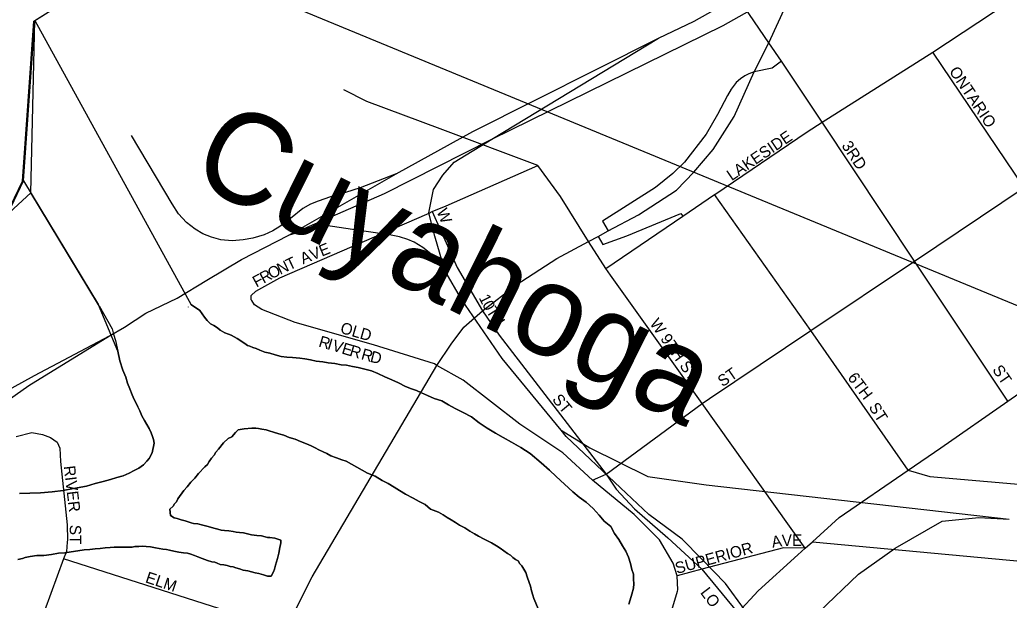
# Model space of a CAD drawing. Extents: x -561 to 1170, y 0 to 846.
# Drawn here: x 229.07 to 240.77, y 285.96 to 292.82 of the extents above; entities that cross this region are included whole.
import ezdxf

# ---------------------------------------------------------------- set-up
doc = ezdxf.new("R2010")
doc.units = 0
for name, color, linetype in [('GM_X_City_Street', 7, 'Continuous'), ('GM_X_City_Street_Text', 7, 'Continuous'), ('GM_X_County', 7, 'Continuous'), ('GM_X_Interchange_Ramps', 7, 'Continuous'), ('GM_X_Major_Lake', 7, 'Continuous'), ('GM_X_Major_River', 7, 'Continuous'), ('GM_X_Major_River_Text', 7, 'Continuous'), ('GM_X_Rail_Line', 7, 'Continuous'), ('GM_X_State_Route', 7, 'Continuous'), ('GM_X_US_Route', 7, 'Continuous'), ('SH_Text', 7, 'Continuous')]:
    doc.layers.add(name, color=color, linetype=linetype)

msp = doc.modelspace()

# ---------------------------------------------------------------- linework, layer by layer
at = {"layer": 'GM_X_City_Street'}
for points in [[(238.558, 291.607), (239.868, 292.434), (242.363, 294.084), (243.61, 294.998), (245.404, 296.163), (246.416, 296.86), (246.465, 296.891)], [(238.076, 292.33), (237.929, 292.546), (237.294, 293.481), (237.222, 293.588), (237.213, 293.601)], [(237.226, 288.342), (238.426, 289.146), (239.65, 289.967), (240.947, 290.836), (243.453, 292.515), (244.706, 293.355)], [(240.969, 290.804), (240.947, 290.836), (239.868, 292.434)], [(238.558, 291.607), (238.076, 292.33)], [(234.043, 291.529), (233.176, 291.853), (232.904, 291.99)], [(235.196, 291.097), (234.043, 291.529)], [(237.289, 290.754), (238.379, 291.494), (238.558, 291.607)], [(240.754, 288.31), (239.65, 289.967), (238.558, 291.607)], [(233.911, 290.535), (233.949, 290.551), (234.111, 290.621), (235.196, 291.097)], [(236.056, 289.8), (235.999, 289.879), (235.797, 290.199), (235.463, 290.729), (235.196, 291.097)], [(236.909, 290.496), (237.286, 290.752), (237.289, 290.754)], [(239.574, 287.497), (238.426, 289.146), (237.286, 290.752)], [(231.815, 289.501), (231.809, 289.51), (231.809, 289.536), (231.809, 289.562), (231.861, 289.613), (232.145, 289.768), (233.886, 290.523), (233.911, 290.535)], [(233.949, 290.551), (234.242, 289.89), (234.542, 289.378), (234.738, 289.09), (236.005, 287.447)], [(235.999, 289.879), (236.909, 290.496)], [(238.358, 286.573), (237.138, 288.283), (236.056, 289.8)], [(235.844, 287.379), (235.491, 287.701), (234.983, 288.04), (234.313, 288.558), (234.004, 288.734), (233.975, 288.751), (233.253, 288.978), (232.327, 289.24), (231.935, 289.394), (231.847, 289.45), (231.815, 289.501)], [(235.844, 287.379), (236.005, 287.447), (237.138, 288.283), (237.226, 288.342)], [(229.029, 287.896), (229.214, 287.941), (229.341, 287.919), (229.434, 287.884), (229.513, 287.827), (229.544, 287.756), (229.553, 287.6), (229.632, 286.849), (229.636, 286.673), (229.634, 286.644)], [(236.005, 287.447), (236.122, 287.273), (236.34, 287.041), (236.733, 286.696), (237.137, 286.325), (237.56, 285.809), (237.794, 285.486), (238.12, 284.963)], [(239.574, 287.497), (239.829, 287.421), (241.875, 287.246)], [(236.847, 286.065), (236.852, 286.081), (236.844, 286.246), (236.796, 286.398), (236.635, 286.673), (236.334, 286.974), (235.844, 287.379)], [(229.634, 286.644), (229.623, 286.536), (229.588, 286.448), (229.364, 285.836)], [(238.444, 286.651), (244.34, 286.102), (244.643, 286.223)], [(238.358, 286.573), (238.1, 286.579), (237.137, 286.325), (236.844, 286.246)], [(232.413, 285.545), (232.215, 285.608), (229.588, 286.448)], [(236.424, 284.721), (236.471, 284.895), (236.475, 284.911), (236.703, 285.579), (236.847, 286.065)]]:
    msp.add_lwpolyline(points, dxfattribs=at)
at = {"layer": 'GM_X_County'}
msp.add_lwpolyline([(228.917, 290.518), (229.103, 290.91), (229.239, 292.802), (229.767, 293.137), (230.178, 293.098), (230.519, 293.193), (230.927, 293.516), (231.298, 293.866), (231.437, 294.095), (231.451, 294.274), (239.814, 300.702), (242.553, 303.852)], dxfattribs=at)
at = {"layer": 'GM_X_Interchange_Ramps'}
for points in [[(238.076, 292.33), (237.966, 292.245), (237.756, 292.202), (237.692, 292.18), (237.642, 292.155), (237.591, 292.12), (237.543, 292.076), (237.481, 291.997), (237.437, 291.924), (237.321, 291.698), (237.188, 291.466), (236.932, 291.137), (236.793, 291.002), (236.589, 290.838), (235.96, 290.437), (236.029, 290.326)], [(235.909, 290.259), (235.967, 290.162), (236.25, 290.266), (236.887, 290.531), (236.909, 290.496)]]:
    msp.add_lwpolyline(points, dxfattribs=at)
at = {"layer": 'GM_X_Major_Lake'}
msp.add_line((229.201, 290.775), (229.251, 292.809), dxfattribs=at)
for points in [[(226.905, 289.371), (227.507, 289.716), (228.09, 289.927), (228.537, 290.164), (228.929, 290.525), (229.115, 290.917), (229.251, 292.809), (229.779, 293.144), (230.19, 293.104), (230.53, 293.2), (230.939, 293.523), (231.31, 293.873), (231.425, 294.063)], [(229.251, 292.809), (229.779, 293.144), (230.19, 293.104), (230.53, 293.2), (230.939, 293.523), (231.31, 293.873), (231.425, 294.063)], [(226.905, 289.371), (227.507, 289.716), (228.09, 289.927), (228.537, 290.164), (229.201, 290.775)]]:
    msp.add_lwpolyline(points, dxfattribs=at)
at = {"layer": 'GM_X_Major_River'}
for points in [[(229.201, 290.775), (229.251, 292.809)], [(229.251, 292.809), (231.099, 289.45)], [(229.251, 292.809), (231.099, 289.45)], [(229.115, 290.917), (230.001, 289.451)], [(230.001, 289.451), (229.201, 290.775)], [(229.07, 287.221), (229.19, 287.223), (229.319, 287.23), (229.455, 287.242), (229.584, 287.254), (229.708, 287.278), (229.86, 287.307), (229.962, 287.34), (230.059, 287.363), (230.145, 287.386), (230.221, 287.408), (230.296, 287.431), (230.366, 287.459), (230.425, 287.492), (230.479, 287.52), (230.533, 287.558), (230.575, 287.602), (230.602, 287.635), (230.639, 287.701), (230.659, 287.815), (230.653, 287.858), (230.642, 287.896), (230.625, 287.939), (230.603, 287.987), (230.575, 288.036), (230.547, 288.084), (230.514, 288.138), (230.492, 288.197), (230.469, 288.246), (230.447, 288.289), (230.425, 288.332), (230.402, 288.386), (230.374, 288.456), (230.346, 288.526), (230.324, 288.596), (230.29, 288.677), (230.256, 288.79), (230.233, 288.904), (230.001, 289.451)], [(230.01, 289.44), (230.164, 289.168), (230.181, 289.104), (230.204, 289.028), (230.233, 288.904), (230.256, 288.79), (230.29, 288.677), (230.324, 288.596), (230.346, 288.526), (230.374, 288.456), (230.402, 288.386), (230.425, 288.332), (230.447, 288.289), (230.469, 288.246), (230.492, 288.197), (230.514, 288.138), (230.547, 288.084), (230.575, 288.036), (230.603, 287.987), (230.625, 287.939), (230.642, 287.896), (230.653, 287.858), (230.659, 287.815), (230.639, 287.701), (230.602, 287.635), (230.575, 287.602), (230.533, 287.558), (230.479, 287.52), (230.425, 287.492), (230.366, 287.459), (230.296, 287.431), (230.221, 287.408), (230.145, 287.386), (230.059, 287.363), (229.962, 287.34), (229.86, 287.307), (229.708, 287.278), (229.584, 287.254), (229.455, 287.242), (229.319, 287.23), (229.19, 287.223), (229.07, 287.221)], [(231.063, 289.427), (231.062, 289.422)], [(236.333, 286.155), (236.327, 286.209), (236.326, 286.269), (236.309, 286.323), (236.292, 286.393), (236.269, 286.469), (236.236, 286.539), (236.197, 286.603), (236.153, 286.678), (236.103, 286.748), (236.059, 286.829), (235.982, 286.893), (235.921, 286.963), (235.85, 287.043), (235.768, 287.118), (235.686, 287.177), (235.609, 287.241), (235.412, 287.423), (235.335, 287.497), (235.236, 287.583), (235.105, 287.695), (234.996, 287.764), (234.887, 287.828), (234.788, 287.881), (234.696, 287.934), (234.597, 287.992), (234.505, 288.056), (234.412, 288.125), (234.313, 288.178), (234.221, 288.226), (234.139, 288.268), (234.063, 288.316), (233.97, 288.342), (233.894, 288.379), (233.823, 288.411), (233.763, 288.437), (233.703, 288.458), (233.633, 288.484), (233.551, 288.527), (233.469, 288.564), (233.387, 288.601), (233.306, 288.638), (233.229, 288.669), (233.137, 288.695), (233.072, 288.711), (233.007, 288.721), (232.936, 288.736), (232.871, 288.741), (232.795, 288.756), (232.719, 288.766), (232.654, 288.776), (232.578, 288.786), (232.508, 288.801), (232.443, 288.811), (232.383, 288.821), (232.296, 288.826), (232.231, 288.83), (232.161, 288.84), (232.09, 288.861), (232.03, 288.877), (231.971, 288.892), (231.911, 288.913), (231.867, 288.934), (231.829, 288.945), (231.791, 288.961), (231.764, 288.971), (231.731, 288.992), (231.644, 289.051), (231.605, 289.072), (231.573, 289.093), (231.54, 289.104), (231.497, 289.12), (231.442, 289.151), (231.409, 289.178), (231.365, 289.205), (231.327, 289.226), (231.289, 289.263), (231.256, 289.306), (231.228, 289.344), (231.201, 289.381), (231.103, 289.45)], [(231.103, 289.45), (231.201, 289.381), (231.228, 289.344), (231.256, 289.306), (231.289, 289.263), (231.327, 289.226), (231.365, 289.205), (231.409, 289.178), (231.442, 289.151), (231.497, 289.12), (231.54, 289.104), (231.573, 289.093), (231.605, 289.072), (231.644, 289.051), (231.731, 288.992), (231.764, 288.971), (231.791, 288.961), (231.829, 288.945), (231.867, 288.934), (231.911, 288.913), (231.971, 288.892), (232.03, 288.877), (232.09, 288.861), (232.161, 288.84), (232.231, 288.83), (232.296, 288.826), (232.383, 288.821), (232.443, 288.811), (232.508, 288.801), (232.578, 288.786), (232.654, 288.776), (232.719, 288.766), (232.795, 288.756), (232.871, 288.741), (232.936, 288.736), (233.007, 288.721), (233.072, 288.711), (233.137, 288.695), (233.229, 288.669), (233.306, 288.638), (233.387, 288.601), (233.469, 288.564), (233.551, 288.527), (233.633, 288.484), (233.703, 288.458), (233.763, 288.437), (233.823, 288.411), (233.894, 288.379), (233.97, 288.342), (234.063, 288.316), (234.139, 288.268), (234.221, 288.226), (234.313, 288.178), (234.412, 288.125), (234.505, 288.056), (234.597, 287.992), (234.696, 287.934), (234.788, 287.881), (234.887, 287.828), (234.996, 287.764), (235.105, 287.695), (235.236, 287.583), (235.335, 287.497), (235.412, 287.423), (235.609, 287.241), (235.686, 287.177), (235.768, 287.118), (235.85, 287.043), (235.921, 286.963), (235.982, 286.893), (236.059, 286.829), (236.103, 286.748), (236.153, 286.678), (236.197, 286.603), (236.236, 286.539), (236.269, 286.469), (236.292, 286.393), (236.309, 286.323), (236.326, 286.269), (236.327, 286.209), (236.333, 286.155)], [(231.627, 286.342), (231.67, 286.332), (231.714, 286.316), (231.768, 286.306), (231.855, 286.285), (231.898, 286.275), (231.953, 286.259), (232.001, 286.244), (232.045, 286.244), (232.071, 286.293), (232.082, 286.326), (232.097, 286.375), (232.107, 286.413), (232.118, 286.451), (232.128, 286.483), (232.133, 286.516), (232.143, 286.559), (232.148, 286.587), (232.153, 286.614), (232.158, 286.641), (232.158, 286.668), (232.087, 286.694), (232.028, 286.699), (232.001, 286.699), (231.973, 286.709), (231.93, 286.719), (231.876, 286.724), (231.811, 286.734), (231.718, 286.755), (231.67, 286.76), (231.632, 286.765), (231.594, 286.77), (231.545, 286.78), (231.491, 286.785), (231.453, 286.789), (231.415, 286.8), (231.366, 286.81), (231.301, 286.831), (231.235, 286.846), (231.176, 286.862), (231.127, 286.867), (231.1, 286.872), (231.073, 286.882), (231.029, 286.898), (230.98, 286.908), (230.931, 286.924), (230.899, 286.934), (230.855, 286.961), (230.848, 287.037), (230.886, 287.07), (230.902, 287.097), (230.923, 287.124), (230.939, 287.157), (231.013, 287.255), (231.051, 287.299), (231.093, 287.354), (231.141, 287.403), (231.184, 287.458), (231.258, 287.535), (231.291, 287.562), (231.312, 287.6), (231.338, 287.639), (231.37, 287.672), (231.391, 287.71), (231.423, 287.743), (231.482, 287.819), (231.535, 287.869), (231.578, 287.891), (231.621, 287.94), (231.653, 287.973), (231.723, 287.985), (231.815, 287.991), (231.864, 287.992), (231.896, 287.987), (231.934, 287.982), (231.983, 287.972), (232.021, 287.961), (232.07, 287.945), (232.135, 287.925), (232.195, 287.909), (232.255, 287.883), (232.326, 287.862), (232.391, 287.836), (232.462, 287.809), (232.516, 287.783), (232.565, 287.762), (232.609, 287.735), (232.658, 287.714), (232.702, 287.693), (232.751, 287.667), (232.816, 287.64), (232.881, 287.619), (232.93, 287.604), (233.181, 287.46), (233.274, 287.424), (233.355, 287.376), (233.426, 287.339), (233.497, 287.296), (233.563, 287.254), (233.634, 287.211), (233.721, 287.164)], [(233.721, 287.164), (233.634, 287.211), (233.563, 287.254), (233.497, 287.296), (233.426, 287.339), (233.355, 287.376), (233.274, 287.424), (233.181, 287.46), (232.93, 287.604), (232.881, 287.619), (232.816, 287.64), (232.751, 287.667), (232.702, 287.693), (232.658, 287.714), (232.609, 287.735), (232.565, 287.762), (232.516, 287.783), (232.462, 287.809), (232.391, 287.836), (232.326, 287.862), (232.255, 287.883), (232.195, 287.909), (232.135, 287.925), (232.07, 287.945), (232.021, 287.961), (231.983, 287.972), (231.934, 287.982), (231.896, 287.987), (231.864, 287.992), (231.815, 287.991), (231.723, 287.985), (231.653, 287.973), (231.621, 287.94), (231.578, 287.891), (231.535, 287.869), (231.482, 287.819), (231.423, 287.743), (231.391, 287.71), (231.37, 287.672), (231.338, 287.639), (231.312, 287.6), (231.291, 287.562), (231.258, 287.535), (231.184, 287.458), (231.141, 287.403), (231.093, 287.354), (231.051, 287.299), (231.013, 287.255), (230.939, 287.157), (230.923, 287.124), (230.902, 287.097), (230.886, 287.07), (230.848, 287.037), (230.855, 286.961), (230.899, 286.934), (230.931, 286.924), (230.98, 286.908), (231.029, 286.898), (231.073, 286.882), (231.1, 286.872), (231.127, 286.867), (231.176, 286.862), (231.235, 286.846), (231.301, 286.831), (231.366, 286.81), (231.415, 286.8), (231.453, 286.789), (231.491, 286.785), (231.545, 286.78), (231.594, 286.77), (231.632, 286.765), (231.67, 286.76), (231.718, 286.755), (231.811, 286.734), (231.876, 286.724), (231.93, 286.719), (231.973, 286.709), (232.001, 286.699), (232.028, 286.699), (232.087, 286.694), (232.158, 286.668), (232.158, 286.641), (232.153, 286.614), (232.148, 286.587), (232.143, 286.559), (232.133, 286.516), (232.128, 286.483), (232.118, 286.451), (232.107, 286.413), (232.097, 286.375), (232.082, 286.326), (232.071, 286.293), (232.045, 286.244), (232.001, 286.244), (231.953, 286.259), (231.898, 286.275), (231.855, 286.285), (231.768, 286.306), (231.714, 286.316), (231.67, 286.332), (231.627, 286.342)], [(233.721, 287.164), (233.792, 287.127), (233.863, 287.09), (233.929, 287.036), (234.021, 286.999), (234.076, 286.968), (234.125, 286.936), (234.174, 286.909), (234.223, 286.877), (234.272, 286.845), (234.332, 286.814), (234.392, 286.776), (234.447, 286.744), (234.496, 286.718), (234.561, 286.681), (234.648, 286.639), (234.709, 286.601), (234.752, 286.575), (234.796, 286.543), (234.84, 286.511), (234.872, 286.49), (234.9, 286.463), (234.933, 286.442), (234.965, 286.426), (234.982, 286.388), (235.009, 286.367), (235.054, 286.286), (235.071, 286.237), (235.093, 286.167), (235.11, 286.124), (235.122, 286.07), (235.139, 286.021), (235.15, 285.978), (235.206, 285.849)], [(235.206, 285.849), (235.15, 285.978), (235.139, 286.021), (235.122, 286.07), (235.11, 286.124), (235.093, 286.167), (235.071, 286.237), (235.054, 286.286), (235.009, 286.367), (234.982, 286.388), (234.965, 286.426), (234.933, 286.442), (234.9, 286.463), (234.872, 286.49), (234.84, 286.511), (234.796, 286.543), (234.752, 286.575), (234.709, 286.601), (234.648, 286.639), (234.561, 286.681), (234.496, 286.718), (234.447, 286.744), (234.392, 286.776), (234.332, 286.814), (234.272, 286.845), (234.223, 286.877), (234.174, 286.909), (234.125, 286.936), (234.076, 286.968), (234.021, 286.999), (233.929, 287.036), (233.863, 287.09), (233.792, 287.127), (233.721, 287.164)], [(229.049, 286.441), (229.103, 286.452), (229.135, 286.463), (229.194, 286.475), (229.275, 286.487), (229.357, 286.488), (229.448, 286.5), (229.529, 286.517), (229.605, 286.518), (229.832, 286.553), (229.902, 286.559), (229.962, 286.566), (230.021, 286.572), (230.081, 286.578), (230.14, 286.584), (230.189, 286.585), (230.227, 286.585), (230.259, 286.585), (230.303, 286.586), (230.33, 286.586), (230.362, 286.587), (230.4, 286.587), (230.432, 286.593), (230.481, 286.594), (230.519, 286.599), (230.568, 286.595), (230.616, 286.59), (230.676, 286.58), (230.763, 286.564), (230.806, 286.56), (230.844, 286.549), (230.893, 286.539), (230.953, 286.529), (231.007, 286.519), (231.056, 286.514), (231.094, 286.503), (231.137, 286.488), (231.176, 286.472), (231.23, 286.451), (231.29, 286.43), (231.344, 286.414), (231.377, 286.409), (231.404, 286.399), (231.442, 286.383), (231.485, 286.378), (231.523, 286.368), (231.561, 286.357), (231.594, 286.352), (231.627, 286.342)], [(231.627, 286.342), (231.594, 286.352), (231.561, 286.357), (231.523, 286.368), (231.485, 286.378), (231.442, 286.383), (231.404, 286.399), (231.377, 286.409), (231.344, 286.414), (231.29, 286.43), (231.23, 286.451), (231.176, 286.472), (231.137, 286.488), (231.094, 286.503), (231.056, 286.514), (231.007, 286.519), (230.953, 286.529), (230.893, 286.539), (230.844, 286.549), (230.806, 286.56), (230.763, 286.564), (230.676, 286.58), (230.616, 286.59), (230.568, 286.595), (230.519, 286.599), (230.481, 286.594), (230.432, 286.593), (230.4, 286.587), (230.362, 286.587), (230.33, 286.586), (230.303, 286.586), (230.259, 286.585), (230.227, 286.585), (230.189, 286.585), (230.14, 286.584), (230.081, 286.578), (230.021, 286.572), (229.962, 286.566), (229.902, 286.559), (229.832, 286.553), (229.605, 286.518), (229.529, 286.517), (229.448, 286.5), (229.357, 286.488), (229.275, 286.487), (229.194, 286.475), (229.135, 286.463), (229.103, 286.452), (229.049, 286.441)], [(236.271, 285.911), (236.287, 285.965), (236.308, 286.03), (236.328, 286.101), (236.333, 286.155)], [(236.333, 286.155), (236.328, 286.101), (236.308, 286.03), (236.287, 285.965), (236.271, 285.911)]]:
    msp.add_lwpolyline(points, dxfattribs=at)
at = {"layer": 'GM_X_Rail_Line'}
for points in [[(234.654, 291.408), (237.388, 292.751), (238.047, 293.123), (238.727, 293.517), (242.724, 296.018), (245.044, 297.473), (248.149, 299.658), (248.75, 300.059), (249.128, 300.27), (249.659, 300.53), (250.018, 300.685), (250.312, 300.799), (250.655, 300.939), (254.511, 302.474), (255.302, 302.782)], [(236.622, 292.601), (237.045, 292.802), (237.79, 293.225), (239.738, 294.393), (240.095, 294.624)], [(233.521, 290.997), (234.43, 291.497), (236.622, 292.601)], [(234.654, 291.408), (236.622, 292.601)], [(233.521, 290.997), (233.095, 290.833), (232.923, 290.778), (232.747, 290.727), (232.6, 290.676), (232.51, 290.639), (232.417, 290.588), (232.274, 290.471), (232.145, 290.377), (232.063, 290.325), (231.963, 290.278), (231.827, 290.237), (231.715, 290.217), (231.584, 290.207), (231.449, 290.217), (231.338, 290.25), (231.235, 290.289), (231.145, 290.344), (231.043, 290.422), (230.947, 290.524), (230.873, 290.643), (230.392, 291.45)], [(232.253, 290.272), (233.384, 290.765), (234.654, 291.408)], [(234.096, 289.854), (233.977, 290.26), (233.909, 290.536), (233.963, 290.811), (234.074, 290.981), (234.208, 291.136), (234.654, 291.408)], [(232.253, 290.272), (233.521, 290.997)], [(234.096, 289.854), (233.951, 290.037), (233.839, 290.128), (233.733, 290.191), (233.66, 290.222), (233.562, 290.253), (233.463, 290.272), (233.221, 290.309), (233.004, 290.342), (232.691, 290.388), (232.253, 290.272)], [(230.134, 289.083), (230.309, 289.186), (230.562, 289.351), (230.932, 289.529), (231.282, 289.741), (231.693, 289.986), (232.253, 290.272)], [(235.472, 287.967), (234.775, 288.817), (234.298, 289.509), (234.096, 289.854)], [(224.719, 285.505), (225.888, 286.342), (227.816, 287.769), (228.285, 288.063), (228.748, 288.344), (229.248, 288.614), (230.134, 289.083)], [(228.401, 287.894), (228.494, 287.988), (228.758, 288.2), (229.179, 288.498), (230.134, 289.083)], [(237.973, 285.304), (237.713, 285.746), (237.414, 286.156), (237.131, 286.45), (236.902, 286.679), (236.51, 286.973), (236.173, 287.287), (235.532, 287.893), (235.472, 287.967)], [(235.472, 287.967), (235.81, 287.759), (236.496, 287.421), (237.188, 287.323), (240.769, 286.918)], [(237.973, 285.304), (238.52, 285.82), (238.988, 286.267), (239.423, 286.575), (239.976, 286.894), (240.411, 286.936), (240.769, 286.918)]]:
    msp.add_lwpolyline(points, dxfattribs=at)
at = {"layer": 'GM_X_State_Route'}
for points in [[(236.029, 290.326), (236.388, 290.514), (236.835, 290.803), (237.041, 291.016), (237.269, 291.285), (237.516, 291.677), (237.756, 292.202), (237.929, 292.546), (238.611, 294.031), (238.824, 294.474), (238.969, 294.692), (239.182, 294.946), (239.471, 295.222), (239.815, 295.476), (240.216, 295.74)], [(231.962, 284.856), (232.215, 285.608), (232.527, 286.237), (234.004, 288.734), (234.171, 288.986), (234.323, 289.185), (234.542, 289.378), (234.942, 289.688), (235.422, 289.997), (235.797, 290.199), (235.909, 290.259), (236.029, 290.326)]]:
    msp.add_lwpolyline(points, dxfattribs=at)
at = {"layer": 'GM_X_US_Route'}
for points in [[(239.96, 287.762), (240.754, 288.31), (241.465, 288.809)], [(238.271, 286.495), (238.358, 286.573), (238.444, 286.651), (238.76, 286.935), (239.574, 287.497), (239.96, 287.762)], [(232.008, 281.109), (232.222, 281.147), (232.35, 281.186), (232.465, 281.234), (232.671, 281.356), (232.857, 281.507), (233.985, 282.57), (235.253, 283.781), (235.771, 284.276), (236.471, 284.895), (237.099, 285.451), (237.56, 285.809), (237.8, 286.071), (238.271, 286.495)]]:
    msp.add_lwpolyline(points, dxfattribs=at)
at = {"layer": 'SH_Text'}
msp.add_lwpolyline([(164.075, 342.421), (260.894, 281.183), (164.075, 321.099)], close=True, dxfattribs=at)

# ---------------------------------------------------------------- texts
at = {"layer": 'GM_X_City_Street_Text'}
for s, rotation, p in [('ONTARIO', 303.9425, (240.053, 292.21)), ('LAKESIDE', 34.1585, (237.488, 290.91)), ('3RD', 303.6901, (238.782, 291.331)), ('W', 292.6069, (233.997, 290.555)), ('AVE', 22.162, (232.42, 289.927)), ('N', 25.7048, (232.151, 289.803)), ('T', 25.3553, (232.258, 289.855)), ('R', 28.5639, (231.954, 289.698)), ('O', 27.7382, (232.047, 289.749)), ('F', 28.569, (231.87, 289.652)), ('1', 296.7606, (234.495, 289.534)), ('0', 298.8406, (234.535, 289.455)), ('T', 302.8211, (234.581, 289.374)), ('H', 304.2578, (234.634, 289.291)), ('W 9TH ST', 305.2157, (236.513, 289.229)), ('OLD', 344.0556, (232.852, 289.12)), ('R', 343.3008, (232.596, 288.959)), ('I', 343.2798, (232.699, 288.928)), ('V', 343.3006, (232.756, 288.911)), ('E', 343.2929, (232.869, 288.877)), ('R', 343.413, (232.961, 288.85)), ('R', 344.0285, (233.099, 288.809)), ('D', 345.2432, (233.205, 288.779)), ('ST', 34.7021, (237.381, 288.475)), ('ST', 304.6908, (240.564, 288.682)), ('6TH', 306.8751, (238.853, 288.588)), ('ST', 309.8092, (235.359, 288.328)), ('ST', 302.7431, (239.103, 288.242)), ('RIVER', 276.7905, (229.591, 287.542)), ('ST', 270, (229.663, 286.85)), ('A', 9.6851, (237.971, 286.578)), ('V', 2.3614, (238.084, 286.597)), ('E', 0.0546, (238.201, 286.602)), ('SUPERIOR', 15.477, (236.841, 286.269)), ('ELM', 341.5675, (230.548, 286.173)), ('L', 307.1705, (237.111, 286.048)), ('O', 307.1869, (237.169, 285.972))]:
    msp.add_text(s, height=0.135, rotation=rotation, dxfattribs=at).set_placement(p)
at = {"layer": 'GM_X_Major_River_Text'}
msp.add_text('Cuyahoga', height=1.0807, rotation=333.5835, dxfattribs=at).set_placement((231.049, 290.934))

doc.saveas('drawing.dxf')
